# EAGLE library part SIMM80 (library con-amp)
AMP connector
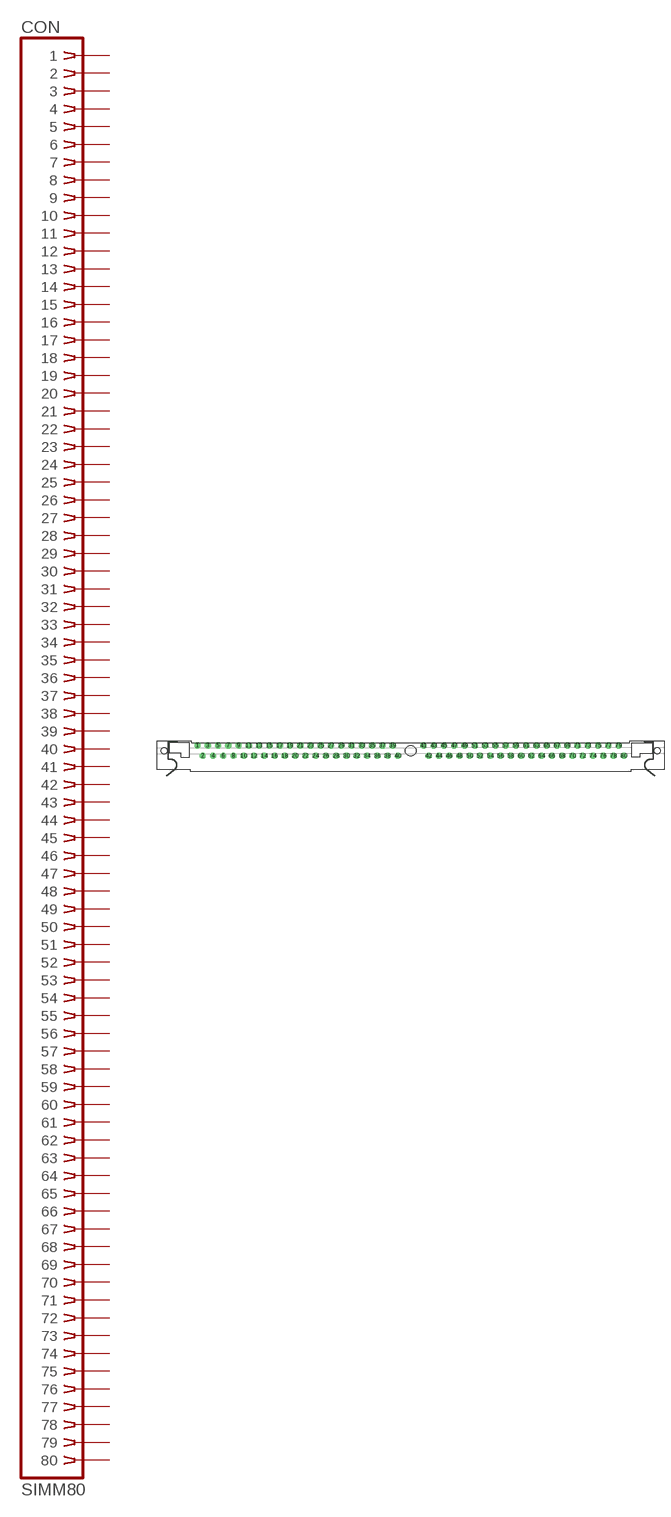
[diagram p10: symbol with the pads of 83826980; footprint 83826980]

Designator prefix CON

## SIMM80 (OC_FARNELL: unknown; OC_NEWARK: unknown)  [83826980]
1  1  pas
2  2  pas
3  3  pas
4  4  pas
5  5  pas
6  6  pas
7  7  pas
8  8  pas
9  9  pas
10  10  pas
11  11  pas
12  12  pas
13  13  pas
14  14  pas
15  15  pas
16  16  pas
17  17  pas
18  18  pas
19  19  pas
20  20  pas
21  21  pas
22  22  pas
23  23  pas
24  24  pas
25  25  pas
26  26  pas
27  27  pas
28  28  pas
29  29  pas
30  30  pas
31  31  pas
32  32  pas
33  33  pas
34  34  pas
35  35  pas
36  36  pas
37  37  pas
38  38  pas
39  39  pas
40  40  pas
41  41  pas
42  42  pas
43  43  pas
44  44  pas
45  45  pas
46  46  pas
47  47  pas
48  48  pas
49  49  pas
50  50  pas
51  51  pas
52  52  pas
53  53  pas
54  54  pas
55  55  pas
56  56  pas
57  57  pas
58  58  pas
59  59  pas
60  60  pas
61  61  pas
62  62  pas
63  63  pas
64  64  pas
65  65  pas
66  66  pas
67  67  pas
68  68  pas
69  69  pas
70  70  pas
71  71  pas
72  72  pas
73  73  pas
74  74  pas
75  75  pas
76  76  pas
77  77  pas
78  78  pas
79  79  pas
80  80  pas

## Footprint 83826980 (pad centres in mm)
SIMM II Socket
drill 1.016 octagon: 1 -52.705,1.27; 2 -51.435,-1.27; 3 -50.165,1.27; 4 -48.895,-1.27; 5 -47.625,1.27; 6 -46.355,-1.27; 7 -45.085,1.27; 8 -43.815,-1.27; 9 -42.545,1.27; 10 -41.275,-1.27; 11 -40.005,1.27; 12 -38.735,-1.27; 13 -37.465,1.27; 14 -36.195,-1.27; 15 -34.925,1.27; 16 -33.655,-1.27; 17 -32.385,1.27; 18 -31.115,-1.27; 19 -29.845,1.27; 20 -28.575,-1.27; 21 -27.305,1.27; 22 -26.035,-1.27; 23 -24.765,1.27; 24 -23.495,-1.27; 25 -22.225,1.27; 26 -20.955,-1.27; 27 -19.685,1.27; 28 -18.415,-1.27; 29 -17.145,1.27; 30 -15.875,-1.27; 31 -14.605,1.27; 32 -13.335,-1.27; 33 -12.065,1.27; 34 -10.795,-1.27; 35 -9.525,1.27; 36 -8.255,-1.27; 37 -6.985,1.27; 38 -5.715,-1.27; 39 -4.445,1.27; 40 -3.175,-1.27; 41 3.175,1.27; 42 4.445,-1.27; 43 5.715,1.27; 44 6.985,-1.27; 45 8.255,1.27; 46 9.525,-1.27; 47 10.795,1.27; 48 12.065,-1.27; 49 13.335,1.27; 50 14.605,-1.27; 51 15.875,1.27; 52 17.145,-1.27; 53 18.415,1.27; 54 19.685,-1.27; 55 20.955,1.27; 56 22.225,-1.27; 57 23.495,1.27; 58 24.765,-1.27; 59 26.035,1.27; 60 27.305,-1.27; 61 28.575,1.27; 62 29.845,-1.27; 63 31.115,1.27; 64 32.385,-1.27; 65 33.655,1.27; 66 34.925,-1.27; 67 36.195,1.27; 68 37.465,-1.27; 69 38.735,1.27; 70 40.005,-1.27; 71 41.275,1.27; 72 42.545,-1.27; 73 43.815,1.27; 74 45.085,-1.27; 75 46.355,1.27; 76 47.625,-1.27; 77 48.895,1.27; 78 50.165,-1.27; 79 51.435,1.27; 80 52.705,-1.27
hole 1.448 at -60.96,0
hole 1.448 at 60.96,0
hole 2.54 at 0,0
